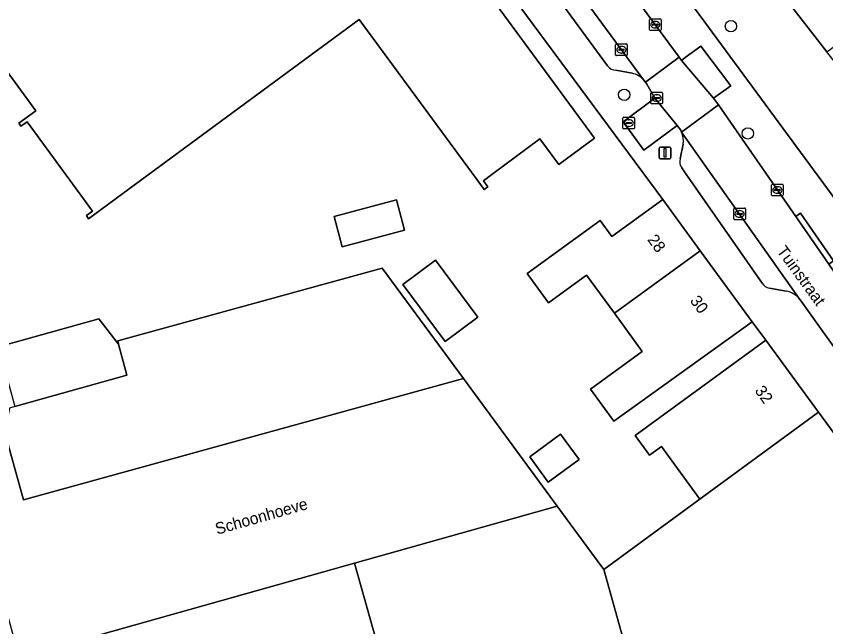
# Model space of a CAD drawing. Extents: x 161798 to 162385, y 382315 to 382833.
# Drawn here: x 161942.5 to 162012.1, y 382382.8 to 382435.2 of the extents above; entities that cross this region are included whole.
import ezdxf

# ---------------------------------------------------------------- set-up
doc = ezdxf.new("R2010")
doc.units = 0
for name, color, linetype in [('IMGEO_Boom', 7, 'Continuous'), ('IMGEO_Brandkraan', 7, 'Continuous'), ('IMGEO_Erf', 7, 'Continuous'), ('IMGEO_Hek', 7, 'Continuous'), ('IMGEO_Kolk', 7, 'Continuous'), ('IMGEO_Lichtmast', 7, 'Continuous'), ('IMGEO_Openbare_ruimte_label', 7, 'Continuous'), ('IMGEO_Pand', 7, 'Continuous'), ('IMGEO_Pand_nummerreeks', 7, 'Continuous'), ('IMGEO_Parkeervlak_open', 7, 'Continuous'), ('IMGEO_Rijbaan_lokaal_open', 7, 'Continuous'), ('IMGEO_Rioolput', 7, 'Continuous'), ('IMGEO_Voetpad_open', 7, 'Continuous')]:
    doc.layers.add(name, color=color, linetype=linetype)

msp = doc.modelspace()

# ---------------------------------------------------------------- linework, layer by layer
at = {"layer": 'IMGEO_Boom'}
for centre in [(162003.926, 382434.351), (161994.753, 382428.459), (162005.374, 382425.139)]:
    msp.add_circle(centre, 0.489, dxfattribs=at)
at = {"layer": 'IMGEO_Brandkraan'}
for p, q in [((161994.641, 382425.6), (161994.641, 382426.452)), ((161994.716, 382426.526), (161995.568, 382426.526)), ((161994.9, 382426.02), (161994.9, 382426.032)), ((161995.338, 382425.983), (161994.94, 382425.983)), ((161994.943, 382426.069), (161995.341, 382426.069)), ((161995.129, 382426.306), (161995.154, 382426.306)), ((161995.384, 382426.032), (161995.384, 382426.02)), ((161995.642, 382426.452), (161995.642, 382425.6)), ((161995.568, 382425.526), (161994.716, 382425.526)), ((161995.152, 382425.746), (161995.127, 382425.746))]:
    msp.add_line(p, q, dxfattribs=at)
for points in [[(161994.641, 382425.6), (161994.641, 382426.452)], [(161994.716, 382426.526), (161995.568, 382426.526)], [(161995.642, 382426.452), (161995.642, 382425.6)], [(161995.568, 382425.526), (161994.716, 382425.526)]]:
    msp.add_lwpolyline(points, dxfattribs=at)
for centre, radius, start, end in [((161994.718, 382426.45), 0.0765, 91.55205, 178.44795), ((161994.718, 382426.45), 0.0765, 91.55205, 178.44795), ((161994.94, 382426.029), 0.0403, 85.87752, 175.75265), ((161994.937, 382426.019), 0.0366, 178.93798, 274.71019), ((161995.341, 382426.026), 0.043, 264.86636, 352.45326), ((161995.345, 382426.031), 0.0386, 1.73085, 96.63898), ((161995.566, 382426.45), 0.0765, 1.55205, 88.44795), ((161995.566, 382426.45), 0.0765, 1.55205, 88.44795), ((161994.718, 382425.602), 0.0765, 181.55205, 268.44795), ((161994.718, 382425.602), 0.0765, 181.55205, 268.44795), ((161995.566, 382425.602), 0.0765, 271.55205, 358.44795), ((161995.566, 382425.602), 0.0765, 271.55205, 358.44795)]:
    msp.add_arc(centre, radius, start, end, dxfattribs=at)
for centre, major_axis, ratio, start_param, end_param in [((161995.128, 382426.026), (-0.387, 0.002), 0.722429, 4.712389, 7.853982), ((161995.153, 382426.026), (-0.39, 0.002), 0.717154, 1.570796, 4.712389)]:
    msp.add_ellipse(centre, major_axis=major_axis, ratio=ratio, start_param=start_param, end_param=end_param, dxfattribs=at)
at = {"layer": 'IMGEO_Erf'}
for points in [[(161992.675, 382417.668), (161993.681, 382416.287), (161998.059, 382419.476), (161983.404, 382439.272), (161954.726, 382478.543), (161954.147, 382478.116), (161955.929, 382475.702), (161949.886, 382471.244), (161948.092, 382473.677), (161947.771, 382473.441), (161945.307, 382476.783), (161945.26, 382476.846), (161940.383, 382473.25)], [(161958.958, 382469.924), (161992.199, 382424.732), (161989.125, 382422.47), (161987.511, 382424.66), (161983.375, 382421.618), (161982.644, 382421.08), (161983.026, 382420.561), (161982.715, 382420.332), (161982.033, 382421.259), (161971.982, 382434.924), (161953.281, 382421.168), (161948.722, 382417.815), (161948.529, 382418.078), (161949.061, 382418.469), (161943.427, 382426.129), (161942.91, 382425.748), (161942.721, 382426.005), (161944.197, 382427.091), (161938.983, 382434.18)], [(161994.413, 382444.586), (162012.934, 382419.392), (162026.252, 382429.136), (162024.941, 382430.922), (162025.905, 382431.677), (162023.078, 382435.482)], [(162020.263, 382438.147), (162022.593, 382434.996), (162020.709, 382433.572), (162024.326, 382428.653), (162018.139, 382424.104), (162015.736, 382427.395), (162013.313, 382430.679), (162012.164, 382432.155), (162005.83, 382440.291)], [(161940.944, 382406.8), (161949.609, 382409.212), (161951.302, 382407.048), (161951.23, 382407.316), (161973.948, 382413.567), (161980.926, 382404.082), (161988.977, 382393.137), (161991.94, 382389.109), (161992.986, 382387.688), (162002.027, 382394.301), (162001.259, 382393.74), (161997.954, 382398.26), (161996.93, 382397.508), (161995.683, 382399.208), (162006.916, 382407.381), (162005.738, 382408.96), (161993.858, 382400.416), (161991.849, 382403.174), (161996.3, 382406.414), (161993.912, 382409.693), (161991.524, 382412.972), (161988.238, 382410.58), (161986.401, 382413.104), (161992.675, 382417.668)]]:
    msp.add_lwpolyline(points, dxfattribs=at)
for points in [[(161975.867, 382416.822), (161970.518, 382415.391), (161969.822, 382417.994), (161975.171, 382419.423)], [(161979.366, 382407.264), (161975.729, 382412.161), (161978.538, 382414.248), (161982.176, 382409.351)], [(161989.286, 382399.316), (161990.883, 382397.138), (161988.225, 382395.188), (161986.627, 382397.366)]]:
    msp.add_lwpolyline(points, close=True, dxfattribs=at)
at = {"layer": 'IMGEO_Hek'}
msp.add_lwpolyline([(161980.926, 382404.082), (161988.977, 382393.137)], dxfattribs=at)
at = {"layer": 'IMGEO_Kolk'}
for p, q in [((161996.916, 382434.049), (161996.916, 382434.901)), ((161996.991, 382434.975), (161997.843, 382434.975)), ((161997.175, 382434.469), (161997.175, 382434.481)), ((161997.613, 382434.432), (161997.215, 382434.432)), ((161997.218, 382434.518), (161997.616, 382434.518)), ((161997.404, 382434.755), (161997.429, 382434.755)), ((161997.659, 382434.481), (161997.659, 382434.469)), ((161997.917, 382434.901), (161997.917, 382434.049)), ((161997.843, 382433.975), (161996.991, 382433.975)), ((161997.427, 382434.195), (161997.402, 382434.195)), ((161994.016, 382431.894), (161994.016, 382432.746)), ((161994.091, 382432.82), (161994.943, 382432.82)), ((161994.275, 382432.314), (161994.275, 382432.326)), ((161994.713, 382432.277), (161994.315, 382432.277)), ((161994.318, 382432.363), (161994.716, 382432.363)), ((161994.504, 382432.6), (161994.529, 382432.6)), ((161994.759, 382432.326), (161994.759, 382432.314)), ((161995.017, 382432.746), (161995.017, 382431.894)), ((161994.943, 382431.82), (161994.091, 382431.82)), ((161994.527, 382432.04), (161994.502, 382432.04)), ((162007.414, 382419.85), (162007.414, 382420.702)), ((162007.489, 382420.776), (162008.341, 382420.776)), ((162007.902, 382420.556), (162007.927, 382420.556)), ((162008.415, 382420.702), (162008.415, 382419.85)), ((162008.341, 382419.776), (162007.489, 382419.776)), ((162007.673, 382420.27), (162007.673, 382420.282)), ((162008.111, 382420.233), (162007.713, 382420.233)), ((162007.716, 382420.319), (162008.114, 382420.319)), ((162007.925, 382419.996), (162007.9, 382419.996)), ((162008.157, 382420.282), (162008.157, 382420.27)), ((162004.165, 382417.803), (162004.165, 382418.655)), ((162004.24, 382418.729), (162005.092, 382418.729)), ((162004.653, 382418.509), (162004.678, 382418.509)), ((162005.166, 382418.655), (162005.166, 382417.803)), ((162005.092, 382417.729), (162004.24, 382417.729)), ((162004.424, 382418.223), (162004.424, 382418.235)), ((162004.862, 382418.186), (162004.464, 382418.186)), ((162004.467, 382418.272), (162004.865, 382418.272)), ((162004.676, 382417.949), (162004.651, 382417.949)), ((162004.908, 382418.235), (162004.908, 382418.223))]:
    msp.add_line(p, q, dxfattribs=at)
for points in [[(161996.916, 382434.049), (161996.916, 382434.901)], [(161996.991, 382434.975), (161997.843, 382434.975)], [(161997.917, 382434.901), (161997.917, 382434.049)], [(161997.843, 382433.975), (161996.991, 382433.975)], [(161994.016, 382431.894), (161994.016, 382432.746)], [(161994.091, 382432.82), (161994.943, 382432.82)], [(161995.017, 382432.746), (161995.017, 382431.894)], [(161994.943, 382431.82), (161994.091, 382431.82)], [(162007.414, 382419.85), (162007.414, 382420.702)], [(162007.489, 382420.776), (162008.341, 382420.776)], [(162008.415, 382420.702), (162008.415, 382419.85)], [(162008.341, 382419.776), (162007.489, 382419.776)], [(162004.165, 382417.803), (162004.165, 382418.655)], [(162004.24, 382418.729), (162005.092, 382418.729)], [(162005.166, 382418.655), (162005.166, 382417.803)], [(162005.092, 382417.729), (162004.24, 382417.729)]]:
    msp.add_lwpolyline(points, dxfattribs=at)
for centre, radius, start, end in [((161996.993, 382434.899), 0.0765, 91.55205, 178.44795), ((161996.993, 382434.899), 0.0765, 91.55205, 178.44795), ((161997.215, 382434.478), 0.0403, 85.87752, 175.75265), ((161997.212, 382434.468), 0.0366, 178.93798, 274.71019), ((161997.616, 382434.475), 0.043, 264.86636, 352.45326), ((161997.62, 382434.48), 0.0386, 1.73085, 96.63898), ((161997.841, 382434.899), 0.0765, 1.55205, 88.44795), ((161997.841, 382434.899), 0.0765, 1.55205, 88.44795), ((161996.993, 382434.051), 0.0765, 181.55205, 268.44795), ((161996.993, 382434.051), 0.0765, 181.55205, 268.44795), ((161997.841, 382434.051), 0.0765, 271.55205, 358.44795), ((161997.841, 382434.051), 0.0765, 271.55205, 358.44795), ((161994.093, 382432.744), 0.0765, 91.55205, 178.44795), ((161994.093, 382432.744), 0.0765, 91.55205, 178.44795), ((161994.315, 382432.323), 0.0403, 85.87752, 175.75265), ((161994.312, 382432.313), 0.0366, 178.93798, 274.71019), ((161994.716, 382432.32), 0.043, 264.86636, 352.45326), ((161994.72, 382432.325), 0.0386, 1.73085, 96.63898), ((161994.941, 382432.744), 0.0765, 1.55205, 88.44795), ((161994.941, 382432.744), 0.0765, 1.55205, 88.44795), ((161994.093, 382431.896), 0.0765, 181.55205, 268.44795), ((161994.093, 382431.896), 0.0765, 181.55205, 268.44795), ((161994.941, 382431.896), 0.0765, 271.55205, 358.44795), ((161994.941, 382431.896), 0.0765, 271.55205, 358.44795), ((162007.491, 382420.7), 0.0765, 91.55205, 178.44795), ((162007.491, 382420.7), 0.0765, 91.55205, 178.44795), ((162008.339, 382420.7), 0.0765, 1.55205, 88.44795), ((162008.339, 382420.7), 0.0765, 1.55205, 88.44795), ((162007.491, 382419.852), 0.0765, 181.55205, 268.44795), ((162007.491, 382419.852), 0.0765, 181.55205, 268.44795), ((162007.713, 382420.279), 0.0403, 85.87752, 175.75265), ((162007.71, 382420.269), 0.0366, 178.93798, 274.71019), ((162008.114, 382420.276), 0.043, 264.86636, 352.45326), ((162008.118, 382420.281), 0.0386, 1.73085, 96.63898), ((162008.339, 382419.852), 0.0765, 271.55205, 358.44795), ((162008.339, 382419.852), 0.0765, 271.55205, 358.44795), ((162004.242, 382418.653), 0.0765, 91.55205, 178.44795), ((162004.242, 382418.653), 0.0765, 91.55205, 178.44795), ((162005.09, 382418.653), 0.0765, 1.55205, 88.44795), ((162005.09, 382418.653), 0.0765, 1.55205, 88.44795), ((162004.242, 382417.805), 0.0765, 181.55205, 268.44795), ((162004.242, 382417.805), 0.0765, 181.55205, 268.44795), ((162004.464, 382418.232), 0.0403, 85.87752, 175.75265), ((162004.461, 382418.222), 0.0366, 178.93798, 274.71019), ((162004.865, 382418.229), 0.043, 264.86636, 352.45326), ((162004.869, 382418.234), 0.0386, 1.73085, 96.63898), ((162005.09, 382417.805), 0.0765, 271.55205, 358.44795), ((162005.09, 382417.805), 0.0765, 271.55205, 358.44795)]:
    msp.add_arc(centre, radius, start, end, dxfattribs=at)
for centre, major_axis, ratio, start_param, end_param in [((161997.403, 382434.475), (-0.387, 0.002), 0.722429, 4.712389, 7.853982), ((161997.428, 382434.475), (-0.39, 0.002), 0.717154, 1.570796, 4.712389), ((161994.503, 382432.32), (-0.387, 0.002), 0.722429, 4.712389, 7.853982), ((161994.528, 382432.32), (-0.39, 0.002), 0.717154, 1.570796, 4.712389), ((162007.901, 382420.276), (-0.387, 0.002), 0.722429, 4.712389, 7.853982), ((162007.926, 382420.276), (-0.39, 0.002), 0.717154, 1.570796, 4.712389), ((162004.652, 382418.229), (-0.387, 0.002), 0.722429, 4.712389, 7.853982), ((162004.677, 382418.229), (-0.39, 0.002), 0.717154, 1.570796, 4.712389)]:
    msp.add_ellipse(centre, major_axis=major_axis, ratio=ratio, start_param=start_param, end_param=end_param, dxfattribs=at)
at = {"layer": 'IMGEO_Lichtmast'}
for p, q in [((161997.762, 382423.062), (161997.762, 382423.862)), ((161997.762, 382423.862), (161997.762, 382423.062)), ((161997.862, 382423.962), (161998.652, 382423.962)), ((161998.652, 382423.962), (161997.862, 382423.962)), ((161998.752, 382423.862), (161998.752, 382423.062)), ((161998.752, 382423.062), (161998.752, 382423.862)), ((161998.652, 382422.962), (161997.862, 382422.962)), ((161997.862, 382422.962), (161998.652, 382422.962))]:
    msp.add_line(p, q, dxfattribs=at)
msp.add_lwpolyline([(161998.182, 382423.837), (161998.332, 382423.837), (161998.332, 382423.087), (161998.182, 382423.087), (161998.182, 382423.837)], dxfattribs=at)
for centre, start, end in [((161997.862, 382423.862), 90, 180), ((161997.862, 382423.862), 90, 180), ((161998.652, 382423.862), 0, 90), ((161998.652, 382423.862), 360, 90), ((161997.862, 382423.062), 180, 270), ((161997.862, 382423.062), 180, 270), ((161998.652, 382423.062), 270, 0), ((161998.652, 382423.062), 270, 0)]:
    msp.add_arc(centre, 0.1, start, end, dxfattribs=at)
at = {"layer": 'IMGEO_Pand'}
msp.add_lwpolyline([(161938.983, 382434.18), (161944.197, 382427.091), (161942.721, 382426.005), (161942.91, 382425.748), (161943.427, 382426.129), (161949.061, 382418.469), (161948.529, 382418.078), (161948.722, 382417.815), (161953.281, 382421.168), (161971.982, 382434.924), (161982.033, 382421.259), (161982.715, 382420.332), (161983.026, 382420.561), (161982.644, 382421.08), (161983.375, 382421.618), (161987.511, 382424.66), (161989.125, 382422.47), (161992.199, 382424.732), (161958.958, 382469.924)], dxfattribs=at)
for points in [[(162019.568, 382440.542), (162016.135, 382445.239), (162013.597, 382443.352), (162012.297, 382445.1), (162006.084, 382440.48), (162005.83, 382440.291), (162012.164, 382432.155), (162018.358, 382436.738), (162017.04, 382438.599)], [(161975.867, 382416.822), (161975.171, 382419.423), (161969.822, 382417.994), (161970.518, 382415.391)], [(162001.282, 382415.062), (161998.059, 382419.476), (161993.681, 382416.287), (161992.675, 382417.668), (161986.401, 382413.104), (161988.238, 382410.58), (161991.524, 382412.972), (161993.912, 382409.693)], [(162001.282, 382415.062), (161993.912, 382409.693), (161996.3, 382406.414), (161991.849, 382403.174), (161993.858, 382400.416), (162005.738, 382408.96)], [(161979.366, 382407.264), (161982.176, 382409.351), (161978.538, 382414.248), (161975.729, 382412.161)], [(161973.948, 382413.567), (161951.23, 382407.316), (161951.302, 382407.048), (161952.02, 382404.363), (161942.37, 382401.676), (161941.909, 382401.548), (161941.516, 382399.444), (161943.116, 382393.678), (161980.926, 382404.082)], [(161951.302, 382407.048), (161949.609, 382409.212), (161940.944, 382406.8), (161942.37, 382401.676), (161952.02, 382404.363)], [(162011.459, 382401.201), (162006.916, 382407.381), (161995.683, 382399.208), (161996.93, 382397.508), (161997.954, 382398.26), (162001.259, 382393.74), (162002.027, 382394.301)], [(161992.986, 382387.688), (161996.279, 382375.983), (162000, 382377.033), (162005.41, 382378.559), (162009.526, 382379.708), (162009.093, 382381.268), (162011.466, 382381.97), (162011.964, 382380.39), (162012.37, 382380.501), (162016.275, 382381.566), (162019.512, 382383.48), (162016.974, 382392.447), (162016.93, 382392.603), (162015.773, 382395.333), (162015.66, 382395.487), (162011.459, 382401.201), (162002.027, 382394.301)], [(161986.627, 382397.366), (161988.225, 382395.188), (161990.883, 382397.138), (161989.286, 382399.316)], [(161992.986, 382387.688), (161991.94, 382389.109), (161988.977, 382393.137), (161971.566, 382388.238), (161976.577, 382370.429), (161979.826, 382371.342), (161991.705, 382374.693), (161994.682, 382375.533), (161996.279, 382375.983)], [(161976.577, 382370.429), (161971.566, 382388.238), (161944.182, 382380.534), (161945.898, 382374.07), (161947.642, 382368.082), (161948.578, 382364.866), (161949.205, 382362.714), (161949.687, 382362.852), (161952.673, 382363.708), (161959.741, 382365.695), (161966.232, 382367.52), (161973.328, 382369.515)]]:
    msp.add_lwpolyline(points, close=True, dxfattribs=at)
at = {"layer": 'IMGEO_Parkeervlak_open'}
for points in [[(161996.412, 382429.744), (161966.539, 382470.379), (161966.741, 382469.631), (161966.415, 382468.203)], [(161966.551, 382467.446), (161993.315, 382430.945)], [(161994.041, 382430.567), (161995.442, 382430.301)], [(162009.841, 382410.886), (161999.682, 382425.259)], [(161999.822, 382424.223), (161999.564, 382422.953)], [(161999.691, 382422.185), (162000, 382421.742), (162006.595, 382412.288)], [(162007.238, 382411.855), (162008.683, 382411.604)], [(161939.23, 382392.79), (161942.76, 382380.116), (161944.182, 382380.534), (161971.566, 382388.238), (161988.977, 382393.137), (161980.926, 382404.082), (161943.116, 382393.678), (161941.516, 382399.444)]]:
    msp.add_lwpolyline(points, dxfattribs=at)
for points in [[(162002.433, 382428.179), (162003.905, 382429.219), (162001.35, 382432.629), (162000, 382431.645), (161999.673, 382431.407), (162000, 382431.025)], [(161999.316, 382425.829), (161997.372, 382428.158), (161994.671, 382426.124), (161996.451, 382423.692)]]:
    msp.add_lwpolyline(points, close=True, dxfattribs=at)
for centre, radius, start, end in [((161994.041, 382431.453), 0.886, 214.98512, 270.00639), ((161995.018, 382428.44), 1.908, 43.09386, 77.17495), ((161997.841, 382424.483), 1.998, 352.53061, 22.8615), ((162000.351, 382422.689), 0.831, 161.4483, 217.33113), ((162007.409, 382412.803), 0.963, 212.32187, 259.76501), ((162008.286, 382409.67), 1.974, 38.01395, 78.38537)]:
    msp.add_arc(centre, radius, start, end, dxfattribs=at)
at = {"layer": 'IMGEO_Rijbaan_lokaal_open'}
for points in [[(161967.008, 382475.225), (161964.496, 382472.499), (161966.099, 382471.022), (161966.539, 382470.379), (161996.412, 382429.744), (161996.57, 382429.553), (161999.468, 382431.685), (161991.637, 382442.328), (161988.124, 382447.103), (161970.053, 382471.662)], [(162013.778, 382411.818), (162012.33, 382413.906), (162009.488, 382418.005), (162002.849, 382427.58), (161999.682, 382425.259), (162009.841, 382410.886), (162009.951, 382410.728), (162018.719, 382398.49), (162018.806, 382398.381), (162028.106, 382385.351)]]:
    msp.add_lwpolyline(points, dxfattribs=at)
msp.add_lwpolyline([(161999.316, 382425.829), (161999.609, 382425.413), (161999.682, 382425.259), (162002.849, 382427.58), (162002.433, 382428.179), (162000, 382431.025), (161999.673, 382431.407), (161999.468, 382431.685), (161996.57, 382429.553), (161996.682, 382429.377), (161997.372, 382428.158)], close=True, dxfattribs=at)
at = {"layer": 'IMGEO_Rioolput'}
for p, q in [((161997.047, 382427.75), (161997.047, 382428.602)), ((161997.122, 382428.676), (161997.974, 382428.676)), ((161997.306, 382428.17), (161997.306, 382428.182)), ((161997.744, 382428.133), (161997.346, 382428.133)), ((161997.349, 382428.219), (161997.747, 382428.219)), ((161997.535, 382428.456), (161997.56, 382428.456)), ((161997.79, 382428.182), (161997.79, 382428.17)), ((161998.048, 382428.602), (161998.048, 382427.75)), ((161997.974, 382427.676), (161997.122, 382427.676)), ((161997.558, 382427.896), (161997.533, 382427.896))]:
    msp.add_line(p, q, dxfattribs=at)
for points in [[(161997.047, 382427.75), (161997.047, 382428.602)], [(161997.122, 382428.676), (161997.974, 382428.676)], [(161998.048, 382428.602), (161998.048, 382427.75)], [(161997.974, 382427.676), (161997.122, 382427.676)]]:
    msp.add_lwpolyline(points, dxfattribs=at)
for centre, radius, start, end in [((161997.124, 382428.6), 0.0765, 91.55205, 178.44795), ((161997.124, 382428.6), 0.0765, 91.55205, 178.44795), ((161997.346, 382428.179), 0.0403, 85.87752, 175.75265), ((161997.343, 382428.169), 0.0366, 178.93798, 274.71019), ((161997.747, 382428.176), 0.043, 264.86636, 352.45326), ((161997.751, 382428.181), 0.0386, 1.73085, 96.63898), ((161997.972, 382428.6), 0.0765, 1.55205, 88.44795), ((161997.972, 382428.6), 0.0765, 1.55205, 88.44795), ((161997.124, 382427.752), 0.0765, 181.55205, 268.44795), ((161997.124, 382427.752), 0.0765, 181.55205, 268.44795), ((161997.972, 382427.752), 0.0765, 271.55205, 358.44795), ((161997.972, 382427.752), 0.0765, 271.55205, 358.44795)]:
    msp.add_arc(centre, radius, start, end, dxfattribs=at)
for centre, major_axis, ratio, start_param, end_param in [((161997.534, 382428.176), (-0.387, 0.002), 0.722429, 4.712389, 7.853982), ((161997.559, 382428.176), (-0.39, 0.002), 0.717154, 1.570796, 4.712389)]:
    msp.add_ellipse(centre, major_axis=major_axis, ratio=ratio, start_param=start_param, end_param=end_param, dxfattribs=at)
at = {"layer": 'IMGEO_Voetpad_open'}
for points in [[(161938.715, 382497.147), (161939.523, 382495.623), (161943.046, 382494.363), (161946.327, 382489.811), (161950.356, 382484.334), (161950.42, 382484.381), (161954.726, 382478.543), (161983.404, 382439.272), (161998.059, 382419.476), (162001.282, 382415.062), (162005.738, 382408.96), (162006.916, 382407.381), (162011.459, 382401.201), (162015.66, 382395.487), (162015.773, 382395.333), (162016.93, 382392.603), (162016.974, 382392.447), (162019.512, 382383.48), (162025.97, 382385.896)], [(161970.053, 382471.662), (161988.124, 382447.103), (161988.526, 382447.399), (161992.039, 382442.624), (161991.637, 382442.328), (161999.468, 382431.685), (161999.673, 382431.407), (162000, 382431.645), (162001.35, 382432.629), (162003.905, 382429.219), (162002.433, 382428.179), (162002.849, 382427.58), (162009.488, 382418.005), (162009.898, 382418.289), (162012.74, 382414.19), (162012.33, 382413.906), (162013.778, 382411.818)], [(161993.315, 382430.945), (161966.551, 382467.446)], [(162033.24, 382387.513), (162033.178, 382387.292), (162032.951, 382386.532), (162032.83, 382385.614), (162037.166, 382386.303), (162033.504, 382391.316), (162029.806, 382396.378), (162026.571, 382400.806), (162023.288, 382405.3), (162022.628, 382406.187), (162018.079, 382412.392), (162015.189, 382416.324), (162012.934, 382419.392), (161994.413, 382444.586)], [(161995.442, 382430.301), (161994.041, 382430.567)], [(161999.682, 382425.259), (161999.609, 382425.413), (161999.316, 382425.829), (161996.451, 382423.692), (161994.671, 382426.124), (161997.372, 382428.158), (161996.682, 382429.377), (161996.57, 382429.553), (161996.412, 382429.744)], [(161999.564, 382422.953), (161999.822, 382424.223)], [(162006.595, 382412.288), (162000, 382421.742), (161999.691, 382422.185)], [(162008.683, 382411.604), (162007.238, 382411.855)], [(162018.719, 382398.49), (162009.951, 382410.728), (162009.841, 382410.886)]]:
    msp.add_lwpolyline(points, dxfattribs=at)
msp.add_lwpolyline([(162009.488, 382418.005), (162012.33, 382413.906), (162012.74, 382414.19), (162009.898, 382418.289)], close=True, dxfattribs=at)
for centre, radius, start, end in [((161994.041, 382431.453), 0.886, 214.98512, 270.00639), ((161995.018, 382428.44), 1.908, 43.09386, 77.17495), ((161997.841, 382424.483), 1.998, 352.53061, 22.8615), ((162000.351, 382422.689), 0.831, 161.4483, 217.33113), ((162007.409, 382412.803), 0.963, 212.32187, 259.76501), ((162008.286, 382409.67), 1.974, 38.01395, 78.38537)]:
    msp.add_arc(centre, radius, start, end, dxfattribs=at)

# ---------------------------------------------------------------- texts
at = {"layer": 'IMGEO_Openbare_ruimte_label'}
for s, rotation, p in [('Tuinstraat', 306.13684, (162007.813, 382415.033)), ('Schoonhoeve', 15.78795, (161959.765, 382390.669))]:
    msp.add_text(s, height=1, rotation=rotation, dxfattribs=at).set_placement(p)
at = {"layer": 'IMGEO_Pand_nummerreeks'}
for s, rotation, p in [('28', 306.16561, (161996.7, 382416.01)), ('30', 306.43086, (162000.36, 382410.759)), ('32', 305.72944, (162005.925, 382403.038))]:
    msp.add_text(s, height=1, rotation=rotation, dxfattribs=at).set_placement(p)

doc.saveas('drawing.dxf')
